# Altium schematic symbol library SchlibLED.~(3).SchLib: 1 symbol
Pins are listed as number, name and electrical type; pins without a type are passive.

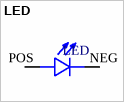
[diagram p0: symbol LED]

## LED
designator LED, comment LHN974_RED_LED_1206  (value not drawn)
2.6 V Red LED SMD; MP: LHN974 RED LED 1206; MF: Osram
footprint LEDC3216X120N
pins: NEG, POS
